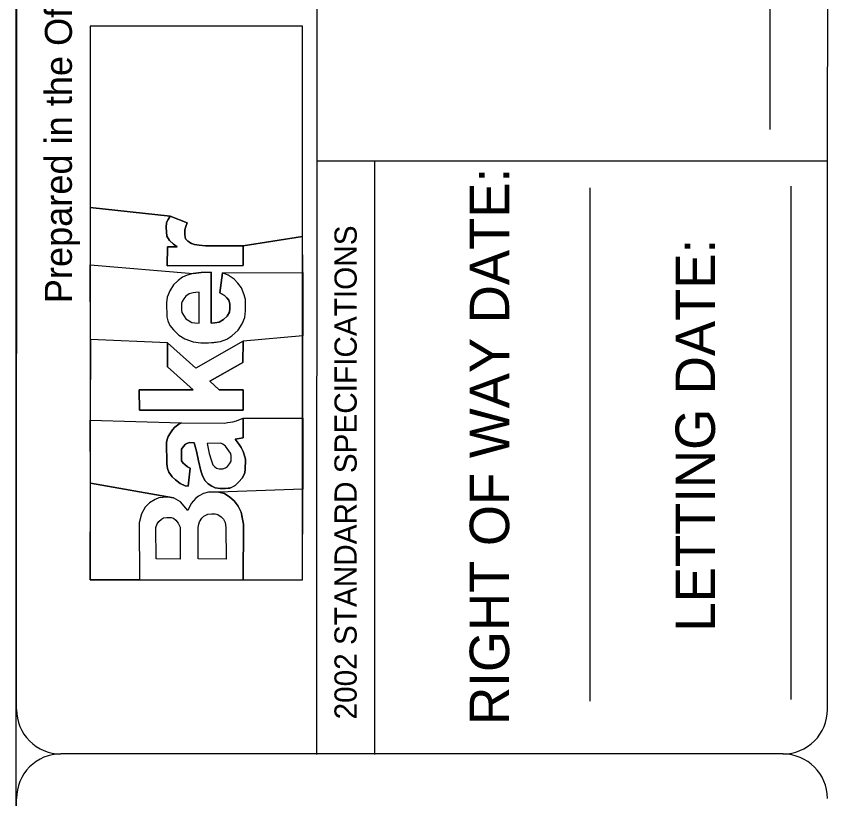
# Model space of a CAD drawing. Extents: x 264770 to 739672, y 157173 to 249791.
# Drawn here: x 732247 to 733478, y 169736 to 170923 of the extents above; entities that cross this region are included whole.
import ezdxf

# ---------------------------------------------------------------- set-up
doc = ezdxf.new("R2010")
doc.units = 0
for name, color, linetype in [('Old_Level_5', 7, 'Continuous'), ('Prop Cable Guiderail Anchor Unit CELL', 7, 'Continuous'), ('Prop GRAU 350 Approach CELL', 7, 'Continuous'), ('Prop SAU III Trailing CELL', 7, 'Continuous'), ('Sheet Plot Border Inside CELL', 7, 'Continuous'), ('Sheet Profile Grid Major CELL', 7, 'Continuous')]:
    doc.layers.add(name, color=color, linetype=linetype)

msp = doc.modelspace()

# ---------------------------------------------------------------- linework, layer by layer
at = {"layer": 'Old_Level_5'}
msp.add_line((733390.9, 170751.2), (733391, 171812.9), dxfattribs=at)
at = {"layer": 'Prop Cable Guiderail Anchor Unit CELL'}
for p, q in [((732790.4, 170443.5), (732790.4, 170443.5)), ((733116.8, 170274.7), (733116.8, 170274.7)), ((733421.7, 170277.3), (733421.7, 170277.3))]:
    msp.add_line(p, q, dxfattribs=at)
at = {"layer": 'Prop GRAU 350 Approach CELL'}
for p, q in [((732247, 164810.5), (732247, 174523.8)), ((732247.6, 169871.2), (732247.9, 171821.7)), ((732315, 169805), (733410.4, 169804.9)), ((732247.2, 166851.5), (732247.6, 169737.5))]:
    msp.add_line(p, q, dxfattribs=at)
msp.add_lwpolyline([(733477.8, 169871), (733478.1, 171822.9)], dxfattribs=at)
for centre, major_axis, start_param, end_param in [((732314.8, 169871.9), (0, 67.5), 1.57067, 3.141467), ((733410.1, 169871.8), (0, -67.5), 6.283059, 7.853856), ((732314.8, 169736.9), (0, 67.5), 6.283059, 7.853856), ((733410.1, 169736.8), (0, 67.5), 4.712263, 6.283059)]:
    msp.add_ellipse(centre, major_axis=major_axis, ratio=0.999289, start_param=start_param, end_param=end_param, dxfattribs=at)
at = {"layer": 'Prop SAU III Trailing CELL'}
for p, q in [((732476.4, 170573.2), (732476, 170544.8)), ((732491.2, 170573.3), (732476.4, 170573.2)), ((732591.2, 170574.9), (732534.1, 170575)), ((732591.1, 170544.9), (732591.2, 170574.9)), ((732476, 170544.8), (732591.1, 170544.9)), ((732476.4, 170427.9), (732476.5, 170391.5)), ((732590.9, 170397.8), (732591, 170430.4)), ((732476.5, 170391.5), (732515.2, 170356.3)), ((732515.2, 170356.3), (732433.5, 170356.5)), ((732433.5, 170356.5), (732434.1, 170325.9)), ((732591.3, 170356.3), (732554.7, 170356.4)), ((732591.3, 170325.9), (732591.3, 170356.3)), ((732434.1, 170325.9), (732591.3, 170325.9)), ((732531.2, 170199.2), (732523.3, 170195.5)), ((732538.4, 170201.2), (732531.2, 170199.2)), ((732554.1, 170201.4), (732538.4, 170201.2)), ((732562.8, 170199.2), (732554.1, 170201.4)), ((732570.9, 170194), (732562.8, 170199.2)), ((732449.3, 170185), (732442.6, 170178.4)), ((732457.5, 170190.3), (732449.3, 170185)), ((732463.5, 170192.9), (732457.5, 170190.3)), ((732485.3, 170192.7), (732475.6, 170193.6)), ((732496.3, 170186.6), (732485.3, 170192.7)), ((732504.5, 170177.2), (732496.3, 170186.6)), ((732519.6, 170192.1), (732512.4, 170184)), ((732523.3, 170195.5), (732519.6, 170192.1)), ((732577.8, 170188.1), (732570.9, 170194)), ((732583.8, 170180.2), (732577.8, 170188.1)), ((732442.6, 170178.4), (732437, 170168.3)), ((732507.1, 170173.5), (732504.5, 170177.2)), ((732512.4, 170184), (732507.1, 170173.5)), ((732588.4, 170171), (732583.8, 170180.2)), ((732437, 170168.3), (732433.6, 170154.9)), ((732589.5, 170162.9), (732588.4, 170171)), ((732591.5, 170153), (732589.5, 170162.9)), ((732433.6, 170154.9), (732434, 170068.3)), ((732459.2, 170100.4), (732458.6, 170147.9)), ((732495.5, 170148.1), (732495.7, 170100)), ((732522.9, 170100.1), (732522.9, 170147.6)), ((732564.9, 170147.6), (732565.2, 170099.9)), ((732591, 170068.2), (732591.5, 170153)), ((732459.2, 170100.2), (732459.2, 170100.4)), ((732495.7, 170100), (732459.2, 170100.2)), ((732565.2, 170099.9), (732522.9, 170100.1)), ((732434, 170068.3), (732591, 170068.2))]:
    msp.add_line(p, q, dxfattribs=at)
for points in [[(732359.1, 170632.9), (732480.4, 170619.9), (732506.5, 170610), (732504.3, 170604), (732502.8, 170599), (732502.7, 170591.7), (732503.8, 170585.4), (732507.3, 170581.9), (732512.6, 170578.5), (732517.5, 170577.1), (732524.3, 170576.1), (732534.1, 170575), (732591.2, 170574.9), (732681.3, 170589.1), (732681.2, 170908), (732359.3, 170908)], [(732359.3, 170908), (732359.3, 170068.2), (732681.3, 170068.2), (732681.2, 170908)], [(732359.1, 170545.9), (732515.2, 170533.1), (732527.6, 170534.7), (732542.7, 170534.8), (732542.6, 170457.7), (732548.4, 170457.9), (732554.7, 170459), (732561.4, 170463.4), (732566.8, 170468.5), (732570.3, 170474.5), (732571, 170479.8), (732571.2, 170486.8), (732569.7, 170492.5), (732566.6, 170496.1), (732562.8, 170499.4), (732555.6, 170503.8), (732560.1, 170533.8), (732681.5, 170534.5), (732681.3, 170589.1), (732591.2, 170574.9), (732591.1, 170544.9), (732476, 170544.8), (732476.4, 170573.2), (732491.2, 170573.3), (732485.6, 170577.2), (732479.7, 170582.8), (732475.6, 170589.5), (732474.7, 170596.1), (732474.3, 170602.8), (732474.9, 170610.1), (732477.3, 170615), (732480.4, 170619.9), (732359.1, 170632.9)], [(732560.1, 170533.8), (732681.5, 170534.5), (732681.7, 170438.5), (732591, 170430.4), (732519.5, 170389.3), (732476.4, 170427.9), (732359.4, 170432.8), (732359.1, 170545.9), (732515.2, 170533.1), (732506.5, 170530.3), (732499.1, 170527.5), (732492.6, 170522.4), (732485.3, 170515.7), (732480.1, 170506.7), (732475.9, 170496.9), (732474.7, 170488.3), (732475.4, 170467.4), (732476.8, 170461), (732479.9, 170453.9), (732485.6, 170447.3), (732493.7, 170439.4), (732502.6, 170433.8), (732515.5, 170429.4), (732526.8, 170427.9), (732538.6, 170427.8), (732556.7, 170430), (732566.5, 170433.6), (732573.8, 170438.4), (732583.7, 170446.9), (732589.7, 170456.5), (732593.6, 170466.2), (732594.8, 170476.1), (732594.9, 170493.4), (732592.7, 170500.4), (732588.8, 170511), (732583.1, 170518.5), (732577.4, 170524.6), (732568.3, 170530.5)], [(732524.7, 170457.5), (732524.6, 170504.7), (732519.5, 170504.3), (732515.5, 170503.8), (732509.3, 170502.3), (732504.5, 170498.6), (732501, 170494.4), (732498.9, 170490.4), (732497.6, 170487.3), (732497.6, 170477.1), (732498.3, 170473.9), (732501.6, 170468.1), (732504.4, 170464.3), (732509.2, 170461.1), (732513.6, 170458.8), (732518.1, 170458.1)], [(732359.3, 170310.5), (732497.9, 170306.3), (732563.3, 170306.2), (732567.7, 170306.8), (732575.4, 170308), (732581, 170309.7), (732587.3, 170311.9), (732591.2, 170313.7), (732681.5, 170313.7), (732681.7, 170438.5), (732591, 170430.4), (732590.9, 170397.8), (732540.7, 170369.8), (732554.7, 170356.4), (732591.3, 170356.3), (732591.3, 170325.9), (732434.1, 170325.9), (732433.5, 170356.5), (732515.2, 170356.3), (732476.5, 170391.5), (732476.4, 170427.9), (732359.4, 170432.8)], [(732485.3, 170192.7), (732359.4, 170215), (732359.3, 170310.5), (732497.9, 170306.3), (732493.5, 170304.4), (732487.8, 170299.9), (732483.8, 170295.9), (732480.8, 170291.1), (732477.6, 170285.7), (732476.1, 170281), (732475, 170276.8), (732475.5, 170244.4), (732476.6, 170237.4), (732478.5, 170231.6), (732483.5, 170224.6), (732488.4, 170220), (732495.6, 170214.5), (732503.1, 170211), (732507.9, 170210.2), (732510.9, 170237.9), (732506.7, 170239.7), (732502.5, 170243.1), (732500.4, 170245.5), (732497.6, 170248.7), (732497.5, 170266.6), (732500.1, 170270.3), (732503.6, 170274), (732506, 170275.4), (732509.7, 170276.5), (732516.9, 170276.4), (732520.2, 170263.7), (732523.6, 170248.8), (732527, 170233.9), (732529.5, 170225.9), (732533.7, 170218.6), (732538, 170214.1), (732543.5, 170210.6), (732549, 170207.9), (732556.4, 170207.1), (732564, 170207), (732571.2, 170207.5), (732578.9, 170211.6), (732584.9, 170216.9), (732589.7, 170222.5), (732593, 170229), (732594.4, 170234.7), (732594.7, 170251.5), (732594, 170254.8), (732591.2, 170263.1), (732588, 170269.2), (732585.4, 170273.6), (732579.3, 170281.6), (732591, 170283.5), (732591.2, 170313.7), (732681.5, 170313.7), (732681.5, 170206.1), (732554.1, 170201.4), (732538.4, 170201.2), (732531.2, 170199.2), (732523.3, 170195.5), (732519.6, 170192.1), (732512.4, 170184), (732507.1, 170173.5), (732504.5, 170177.2), (732496.3, 170186.6)], [(732536.7, 170275.4), (732539.9, 170260.2), (732542.7, 170250.6), (732545.4, 170242.6), (732548.1, 170239.9), (732550.7, 170237.8), (732554.9, 170236.7), (732560.2, 170236.7), (732564.6, 170238.1), (732567.5, 170240.4), (732570.5, 170244.2), (732572.8, 170248.4), (732573.2, 170256.8), (732572.1, 170260.6), (732569.7, 170264.2), (732564.3, 170271.2), (732560.4, 170274.3), (732557.5, 170275.7)], [(732485.3, 170192.7), (732475.6, 170193.6), (732469.3, 170193.1), (732463.5, 170192.9), (732457.5, 170190.3), (732449.3, 170185), (732442.6, 170178.4), (732437, 170168.3), (732433.6, 170154.9), (732434, 170068.3), (732359.3, 170068.2), (732359.4, 170215)], [(732554.1, 170201.4), (732562.8, 170199.2), (732570.9, 170194), (732577.8, 170188.1), (732583.8, 170180.2), (732588.4, 170171), (732591.5, 170153), (732591, 170068.2), (732681.3, 170068.2), (732681.5, 170206.1)], [(732459.2, 170100.4), (732458.6, 170147.9), (732460.6, 170153.4), (732463.2, 170157.1), (732467.3, 170160.3), (732470.4, 170162.4), (732475.4, 170162.9), (732481.9, 170163), (732485.7, 170161.8), (732489, 170158.8), (732492.5, 170154.4), (732494.4, 170150.4), (732495.5, 170148.1), (732495.7, 170100)], [(732522.9, 170100.1), (732522.9, 170147.6), (732523.8, 170152.9), (732525.2, 170156.2), (732528.6, 170162), (732531.6, 170165.1), (732534.6, 170166.6), (732537.6, 170167.9), (732543.4, 170168.6), (732548.6, 170168.3), (732552.9, 170167.6), (732557.8, 170164.2), (732561.4, 170160.4), (732563.8, 170155.2), (732564.9, 170147.6), (732565.2, 170099.9)]]:
    msp.add_lwpolyline(points, close=True, dxfattribs=at)
for points in [[(732534.1, 170575), (732524.3, 170576.1), (732517.5, 170577.1), (732512.6, 170578.5), (732507.3, 170581.9), (732503.8, 170585.4), (732502.7, 170591.7), (732502.8, 170599), (732504.3, 170604), (732506.5, 170610), (732480.4, 170619.9), (732477.3, 170615), (732474.9, 170610.1), (732474.3, 170602.8), (732474.7, 170596.1), (732475.6, 170589.5), (732479.7, 170582.8), (732485.6, 170577.2), (732491.2, 170573.3)], [(732542.6, 170457.7), (732542.7, 170534.8), (732527.6, 170534.7), (732515.2, 170533.1), (732506.5, 170530.3), (732499.1, 170527.5), (732492.6, 170522.4), (732485.3, 170515.7), (732480.1, 170506.7), (732475.9, 170496.9), (732474.7, 170488.3), (732475.4, 170467.4), (732476.8, 170461), (732479.9, 170453.9), (732485.6, 170447.3), (732493.7, 170439.4), (732502.6, 170433.8), (732515.5, 170429.4), (732526.8, 170427.9), (732538.6, 170427.8), (732546.8, 170428.5), (732556.7, 170430), (732566.5, 170433.6), (732573.8, 170438.4), (732583.7, 170446.9), (732589.7, 170456.5), (732593.6, 170466.2), (732594.8, 170476.1), (732594.9, 170493.4), (732592.7, 170500.4), (732588.8, 170511), (732583.1, 170518.5), (732577.4, 170524.6), (732568.3, 170530.5), (732560.1, 170533.8), (732555.6, 170503.8), (732562.8, 170499.4), (732566.6, 170496.1), (732569.7, 170492.5), (732571.2, 170486.8), (732571, 170479.8), (732570.3, 170474.5), (732566.8, 170468.5), (732561.4, 170463.4), (732554.7, 170459), (732548.4, 170457.9), (732542.6, 170457.7)], [(732524.7, 170457.5), (732524.6, 170504.7), (732519.5, 170504.3), (732515.5, 170503.8), (732509.3, 170502.3), (732504.5, 170498.6), (732501, 170494.4), (732498.9, 170490.4), (732497.6, 170487.3), (732497.6, 170477.1), (732498.3, 170473.9), (732501.6, 170468.1), (732504.4, 170464.3), (732509.2, 170461.1), (732513.6, 170458.8), (732518.1, 170458.1), (732524.7, 170457.5)], [(732591, 170430.4), (732519.5, 170389.3), (732476.4, 170427.9)], [(732554.7, 170356.4), (732540.7, 170369.8), (732590.9, 170397.8)], [(732510.9, 170237.9), (732507.9, 170210.2), (732503.1, 170211), (732495.6, 170214.5), (732488.4, 170220), (732483.5, 170224.6), (732478.5, 170231.6), (732476.6, 170237.4), (732475.5, 170244.4), (732475, 170276.8), (732476.1, 170281), (732477.6, 170285.7), (732480.8, 170291.1), (732483.8, 170295.9), (732487.8, 170299.9), (732493.5, 170304.4), (732497.9, 170306.3), (732563.3, 170306.2), (732567.7, 170306.8), (732575.4, 170308), (732581, 170309.7), (732587.3, 170311.9), (732591.2, 170313.7), (732591, 170283.5), (732579.3, 170281.6), (732585.4, 170273.6), (732588, 170269.2), (732591.2, 170263.1), (732594, 170254.8), (732594.7, 170251.5), (732594.4, 170234.7), (732593, 170229), (732589.7, 170222.5), (732584.9, 170216.9), (732578.9, 170211.6), (732574.4, 170209.1), (732571.2, 170207.5), (732568.4, 170207.4), (732564, 170207), (732556.4, 170207.1), (732549, 170207.9), (732543.5, 170210.6), (732538, 170214.1), (732533.7, 170218.6), (732529.5, 170225.9), (732527, 170233.9), (732523.6, 170248.8), (732520.2, 170263.7), (732516.9, 170276.4), (732509.7, 170276.5), (732506, 170275.4), (732503.6, 170274), (732500.1, 170270.3), (732497.5, 170266.6), (732497.6, 170248.7), (732500.4, 170245.5), (732502.5, 170243.1), (732506.7, 170239.7), (732510.9, 170237.9)], [(732536.7, 170275.4), (732539.9, 170260.2), (732542.7, 170250.6), (732545.4, 170242.6), (732548.1, 170239.9), (732550.7, 170237.8), (732554.9, 170236.7), (732560.2, 170236.7), (732564.6, 170238.1), (732567.5, 170240.4), (732570.5, 170244.2), (732572.8, 170248.4), (732573.2, 170256.8), (732572.1, 170260.6), (732569.7, 170264.2), (732564.3, 170271.2), (732560.4, 170274.3), (732557.5, 170275.7), (732536.7, 170275.4)], [(732475.6, 170193.6), (732469.3, 170193.1), (732463.5, 170192.9)], [(732458.6, 170147.9), (732460.6, 170153.4), (732463.2, 170157.1), (732467.3, 170160.3), (732470.4, 170162.4), (732475.4, 170162.9), (732481.9, 170163), (732485.7, 170161.8), (732489, 170158.8), (732492.5, 170154.4), (732494.4, 170150.4), (732495.5, 170148.1)], [(732522.9, 170147.6), (732523.8, 170152.9), (732525.2, 170156.2), (732528.6, 170162), (732531.6, 170165.1), (732534.6, 170166.6), (732537.6, 170167.9), (732543.4, 170168.6), (732548.6, 170168.3), (732552.9, 170167.6), (732557.8, 170164.2), (732561.4, 170160.4), (732563.8, 170155.2), (732564.9, 170147.6)]]:
    msp.add_lwpolyline(points, dxfattribs=at)
at = {"layer": 'Sheet Plot Border Inside CELL'}
for p, q in [((732702.9, 171889.2), (732702.7, 169803.6)), ((732790.5, 170704), (732790.3, 169803.6))]:
    msp.add_line(p, q, dxfattribs=at)
at = {"layer": 'Sheet Profile Grid Major CELL'}
for p, q in [((732702.8, 170704), (733477.9, 170703.9)), ((733422.2, 170665.6), (733422.1, 169887.1)), ((733117.2, 170662.9), (733117.1, 169884.4))]:
    msp.add_line(p, q, dxfattribs=at)

# ---------------------------------------------------------------- texts
for s, height, rotation, p in [('Prepared in the Office of:', 40.993, 89.9928, (732331.4, 170488)), ('RIGHT OF WAY DATE: ', 59.838, 89.994, (732994.7, 169848.5)), ('2002 STANDARD SPECIFICATIONS', 33.717, 89.9928, (732763.4, 169856.7)), ('LETTING DATE:', 59.838, 89.994, (733306.9, 169989.8))]:
    msp.add_text(s, height=height, rotation=rotation, dxfattribs=at).set_placement(p)

doc.saveas('drawing.dxf')
